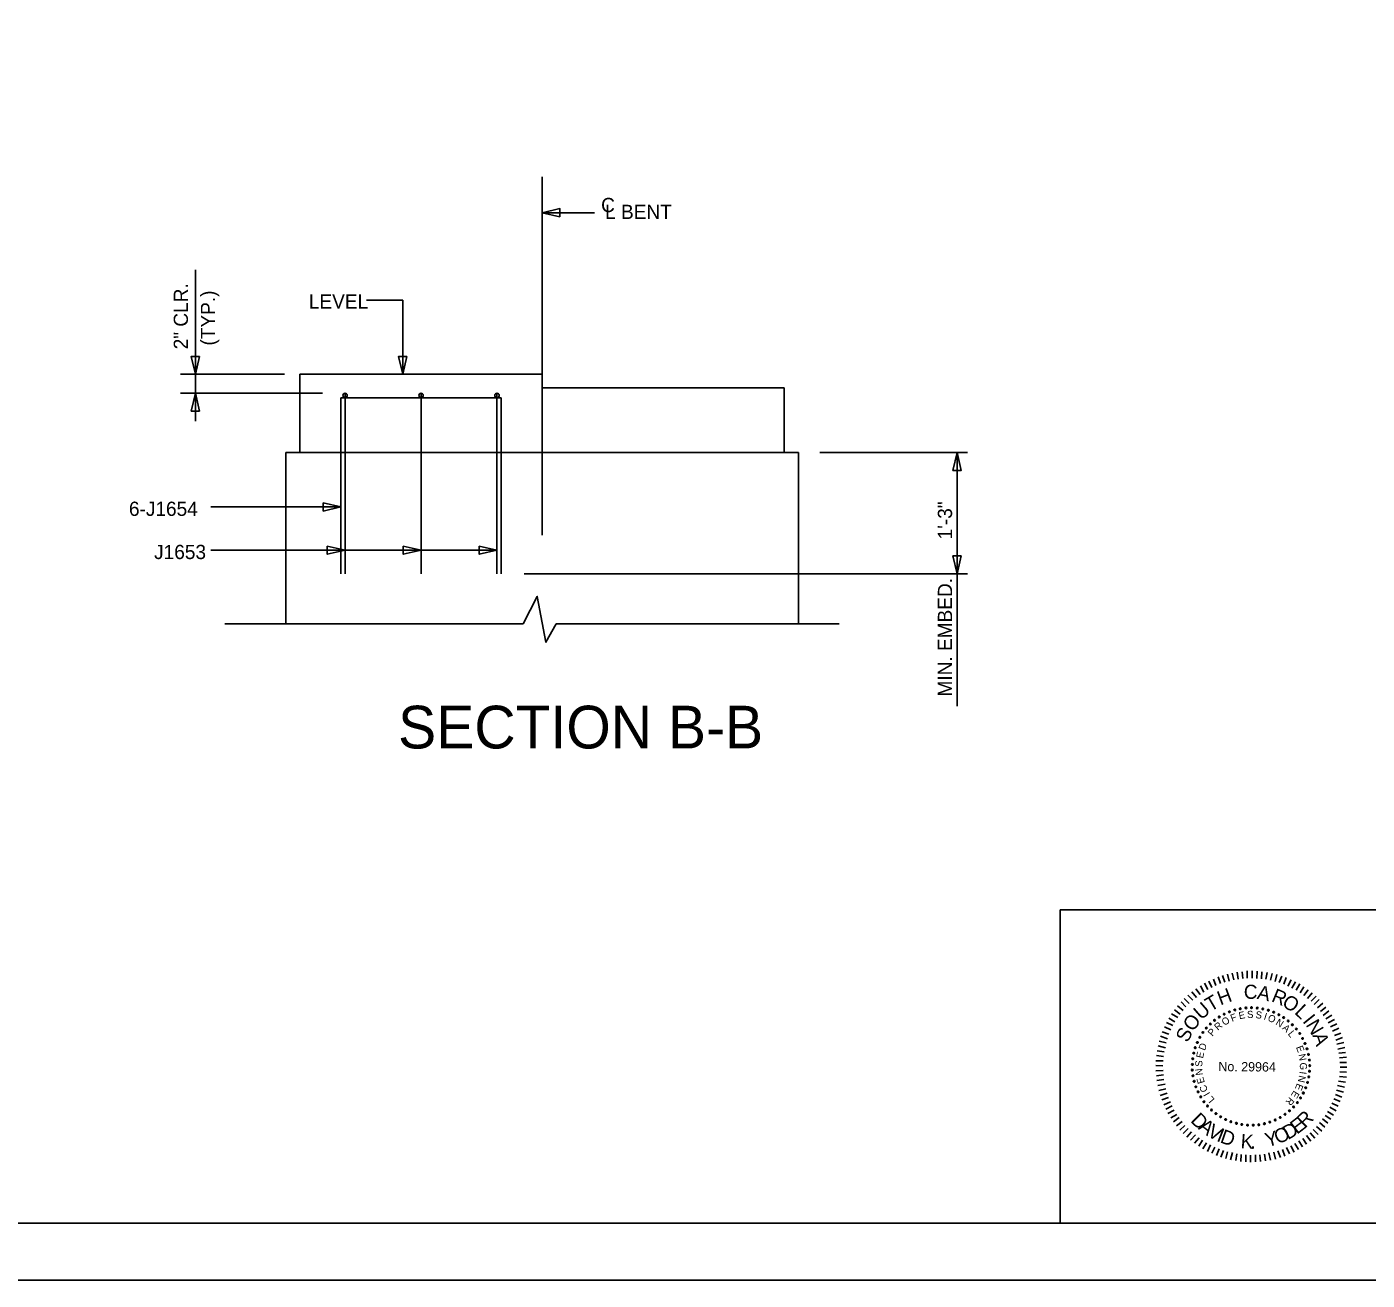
# Model space of a CAD drawing. Extents: x -133.1 to -97, y -58.4 to -36.4.
# Drawn here: x -119.58 to -107.81, y -58.4 to -47.4 of the extents above; entities that cross this region are included whole.
import ezdxf

# ---------------------------------------------------------------- set-up
doc = ezdxf.new("R2010")
doc.units = 0
for name, color, linetype in [('BR_AUTO DIMENSION', 7, 'Continuous'), ('BR_BORDER LINES', 7, 'Continuous'), ('BR_CENTER LINES', 7, 'Continuous'), ('BR_CONCRETE', 7, 'Continuous'), ('BR_REBAR', 7, 'Continuous'), ('BR_TEXT', 7, 'Continuous'), ('Default', 7, 'Continuous'), ('Level 31', 7, 'Continuous')]:
    doc.layers.add(name, color=color, linetype=linetype)

msp = doc.modelspace()

# ---------------------------------------------------------------- linework, layer by layer
at = {"layer": 'BR_AUTO DIMENSION'}
for p, q in [((-115.055, -49.03), (-114.595, -49.03)), ((-118.098, -49.531), (-118.098, -50.859)), ((-116.595, -49.798), (-116.278, -49.798)), ((-116.278, -49.798), (-116.278, -50.448)), ((-117.315, -50.448), (-118.229, -50.448)), ((-116.982, -50.615), (-118.229, -50.615)), ((-112.618, -51.136), (-111.323, -51.136)), ((-111.413, -51.136), (-111.413, -53.362)), ((-116.82, -51.612), (-117.962, -51.612)), ((-115.451, -51.992), (-117.962, -51.992)), ((-116.992, -51.992), (-117.072, -51.992)), ((-116.117, -51.992), (-116.197, -51.992)), ((-115.451, -51.992), (-115.531, -51.992)), ((-115.213, -52.198), (-111.323, -52.198))]:
    msp.add_line(p, q, dxfattribs=at)
for points in [[(-114.899, -49.066), (-115.055, -49.03), (-114.899, -48.994)], [(-118.062, -50.292), (-118.098, -50.448), (-118.134, -50.292)], [(-116.242, -50.292), (-116.278, -50.448), (-116.314, -50.292)], [(-118.134, -50.771), (-118.098, -50.615), (-118.062, -50.771)], [(-111.449, -51.292), (-111.413, -51.136), (-111.377, -51.292)], [(-116.976, -51.576), (-116.82, -51.612), (-116.976, -51.648)], [(-116.94, -51.956), (-116.784, -51.992), (-116.94, -52.028)], [(-116.273, -51.956), (-116.117, -51.992), (-116.273, -52.028)], [(-115.607, -51.956), (-115.451, -51.992), (-115.607, -52.028)], [(-111.377, -52.042), (-111.413, -52.198), (-111.449, -52.042)]]:
    msp.add_lwpolyline(points, close=True, dxfattribs=at)
at = {"layer": 'BR_BORDER LINES'}
for p, q in [((-110.507, -55.149), (-105.142, -55.149)), ((-110.507, -57.899), (-110.507, -55.149)), ((-131.308, -57.899), (-97.642, -57.899))]:
    msp.add_line(p, q, dxfattribs=at)
at = {"layer": 'BR_CENTER LINES'}
msp.add_line((-115.055, -51.86), (-115.055, -48.715), dxfattribs=at)
at = {"layer": 'BR_CONCRETE'}
for p, q in [((-117.18, -50.448), (-117.18, -51.136)), ((-117.18, -50.448), (-115.055, -50.448)), ((-115.055, -50.448), (-115.055, -51.136)), ((-115.055, -50.566), (-112.93, -50.566)), ((-112.93, -50.566), (-112.93, -51.136)), ((-117.305, -52.638), (-117.305, -51.136)), ((-117.305, -51.136), (-112.805, -51.136)), ((-117.305, -51.136), (-112.805, -51.136)), ((-112.805, -52.638), (-112.805, -51.136))]:
    msp.add_line(p, q, dxfattribs=at)
at = {"layer": 'BR_REBAR'}
for p, q in [((-116.82, -50.654), (-116.82, -52.198)), ((-116.82, -50.654), (-115.414, -50.654)), ((-116.784, -50.615), (-116.784, -52.198)), ((-116.117, -50.615), (-116.117, -52.198)), ((-115.451, -50.615), (-115.451, -52.198)), ((-115.414, -50.654), (-115.414, -52.198))]:
    msp.add_line(p, q, dxfattribs=at)
for centre in [(-116.784, -50.634), (-116.117, -50.634), (-115.451, -50.634)]:
    msp.add_circle(centre, 0.0195, dxfattribs=at)
at = {"layer": 'BR_TEXT'}
for p, q in [((-116.278, -50.448), (-116.278, -50.383)), ((-109.141, -55.812), (-109.164, -55.756)), ((-109.102, -55.795), (-109.123, -55.737)), ((-109.062, -55.783), (-109.084, -55.725)), ((-109.026, -55.773), (-109.039, -55.712)), ((-108.985, -55.763), (-108.999, -55.704)), ((-108.945, -55.756), (-108.954, -55.695)), ((-108.906, -55.752), (-108.91, -55.691)), ((-108.866, -55.749), (-108.866, -55.685)), ((-108.824, -55.747), (-108.824, -55.685)), ((-108.782, -55.75), (-108.78, -55.686)), ((-108.742, -55.753), (-108.737, -55.692)), ((-108.703, -55.758), (-108.693, -55.697)), ((-108.663, -55.766), (-108.649, -55.706)), ((-108.622, -55.776), (-108.606, -55.715)), ((-108.585, -55.787), (-108.563, -55.73)), ((-108.546, -55.8), (-108.524, -55.742)), ((-109.312, -55.917), (-109.352, -55.867)), ((-109.279, -55.892), (-109.318, -55.841)), ((-109.248, -55.871), (-109.278, -55.816)), ((-109.212, -55.847), (-109.243, -55.793)), ((-109.178, -55.829), (-109.204, -55.773)), ((-108.51, -55.817), (-108.482, -55.762)), ((-108.474, -55.835), (-108.443, -55.779)), ((-108.436, -55.853), (-108.404, -55.799)), ((-108.403, -55.878), (-108.369, -55.824)), ((-108.37, -55.899), (-108.333, -55.849)), ((-108.337, -55.925), (-108.297, -55.876)), ((-109.429, -56.031), (-109.479, -55.992)), ((-109.404, -56), (-109.447, -55.957)), ((-109.375, -55.969), (-109.419, -55.925)), ((-109.345, -55.942), (-109.387, -55.897)), ((-108.306, -55.95), (-108.263, -55.906)), ((-108.278, -55.978), (-108.235, -55.935)), ((-108.25, -56.009), (-108.202, -55.968)), ((-109.501, -56.13), (-109.555, -56.098)), ((-109.477, -56.094), (-109.531, -56.06)), ((-109.455, -56.065), (-109.505, -56.025)), ((-108.223, -56.041), (-108.176, -56.003)), ((-108.199, -56.075), (-108.15, -56.036)), ((-108.177, -56.104), (-108.124, -56.072)), ((-108.155, -56.141), (-108.101, -56.11)), ((-109.554, -56.24), (-109.612, -56.218)), ((-109.536, -56.201), (-109.593, -56.176)), ((-109.519, -56.164), (-109.575, -56.137)), ((-108.137, -56.176), (-108.079, -56.149)), ((-108.119, -56.213), (-108.062, -56.188)), ((-109.585, -56.358), (-109.648, -56.342)), ((-109.578, -56.316), (-109.639, -56.301)), ((-109.566, -56.28), (-109.627, -56.257)), ((-108.102, -56.252), (-108.046, -56.231)), ((-108.089, -56.292), (-108.031, -56.27)), ((-108.079, -56.328), (-108.019, -56.314)), ((-109.601, -56.435), (-109.662, -56.428)), ((-109.596, -56.394), (-109.657, -56.386)), ((-108.071, -56.37), (-108.011, -56.355)), ((-108.063, -56.406), (-108.003, -56.399)), ((-108.056, -56.448), (-107.995, -56.441)), ((-109.604, -56.558), (-109.669, -56.56)), ((-109.604, -56.474), (-109.668, -56.474)), ((-109.606, -56.516), (-109.668, -56.515)), ((-108.055, -56.487), (-107.995, -56.488)), ((-108.055, -56.571), (-107.995, -56.573)), ((-108.052, -56.528), (-107.991, -56.529)), ((-109.602, -56.597), (-109.664, -56.604)), ((-109.598, -56.638), (-109.659, -56.647)), ((-109.588, -56.678), (-109.651, -56.691)), ((-108.073, -56.69), (-108.013, -56.705)), ((-108.065, -56.651), (-108.005, -56.661)), ((-108.057, -56.61), (-107.996, -56.618)), ((-109.582, -56.72), (-109.643, -56.734)), ((-109.57, -56.757), (-109.632, -56.778)), ((-109.558, -56.796), (-109.617, -56.817)), ((-108.107, -56.808), (-108.051, -56.83)), ((-108.093, -56.769), (-108.036, -56.791)), ((-108.082, -56.732), (-108.022, -56.747)), ((-109.541, -56.833), (-109.599, -56.86)), ((-109.524, -56.869), (-109.581, -56.899)), ((-109.508, -56.906), (-109.562, -56.937)), ((-108.161, -56.917), (-108.108, -56.949)), ((-108.143, -56.88), (-108.086, -56.911)), ((-108.125, -56.844), (-108.068, -56.872)), ((-109.484, -56.943), (-109.538, -56.974)), ((-109.463, -56.972), (-109.513, -57.009)), ((-109.437, -57.006), (-109.487, -57.045)), ((-109.413, -57.04), (-109.457, -57.081)), ((-108.258, -57.049), (-108.212, -57.091)), ((-108.231, -57.016), (-108.185, -57.056)), ((-108.206, -56.983), (-108.158, -57.02)), ((-108.184, -56.954), (-108.132, -56.986)), ((-109.384, -57.066), (-109.429, -57.111)), ((-109.355, -57.096), (-109.397, -57.142)), ((-109.322, -57.122), (-109.363, -57.169)), ((-109.289, -57.148), (-109.329, -57.196)), ((-109.258, -57.17), (-109.29, -57.222)), ((-108.38, -57.156), (-108.345, -57.204)), ((-108.347, -57.13), (-108.308, -57.178)), ((-108.315, -57.105), (-108.273, -57.151)), ((-108.287, -57.075), (-108.244, -57.121)), ((-109.223, -57.192), (-109.255, -57.246)), ((-109.189, -57.212), (-109.216, -57.268)), ((-109.152, -57.23), (-109.177, -57.285)), ((-109.114, -57.247), (-109.136, -57.304)), ((-109.075, -57.26), (-109.097, -57.318)), ((-109.039, -57.272), (-109.053, -57.331)), ((-108.997, -57.279), (-109.013, -57.341)), ((-108.676, -57.282), (-108.662, -57.344)), ((-108.634, -57.275), (-108.619, -57.335)), ((-108.597, -57.264), (-108.576, -57.322)), ((-108.558, -57.252), (-108.537, -57.309)), ((-108.522, -57.235), (-108.495, -57.291)), ((-108.485, -57.218), (-108.455, -57.274)), ((-108.448, -57.199), (-108.416, -57.253)), ((-108.414, -57.177), (-108.381, -57.229)), ((-108.958, -57.291), (-108.968, -57.349)), ((-108.919, -57.295), (-108.923, -57.357)), ((-108.879, -57.298), (-108.88, -57.36)), ((-108.837, -57.301), (-108.838, -57.362)), ((-108.795, -57.299), (-108.794, -57.361)), ((-108.755, -57.297), (-108.751, -57.358)), ((-108.716, -57.293), (-108.706, -57.351))]:
    msp.add_line(p, q, dxfattribs=at)
for centre, start, end in [((-109.153, -56.117), 38.2961, 218.2961), ((-109.112, -56.088), 32.7576, 212.7576), ((-109.112, -56.088), 212.7576, 32.7576), ((-109.069, -56.064), 27.2191, 207.2191), ((-109.069, -56.064), 207.2191, 27.2191), ((-109.023, -56.043), 21.6807, 201.6807), ((-109.023, -56.043), 201.6807, 21.6807), ((-108.976, -56.027), 16.1422, 196.1422), ((-108.976, -56.027), 196.1422, 16.1422), ((-108.928, -56.016), 10.6038, 190.6038), ((-108.928, -56.016), 190.6038, 10.6038), ((-108.878, -56.009), 5.0653, 185.0653), ((-108.878, -56.009), 185.0653, 5.0653), ((-108.829, -56.007), 359.5268, 179.5268), ((-108.829, -56.007), 179.5268, 359.5268), ((-108.779, -56.01), 353.9884, 173.9884), ((-108.779, -56.01), 173.9884, 353.9884), ((-108.73, -56.018), 168.4499, 348.4499), ((-108.73, -56.018), 348.4499, 168.4499), ((-108.681, -56.03), 342.9114, 162.9114), ((-108.681, -56.03), 162.9114, 342.9114), ((-108.635, -56.047), 157.373, 337.373), ((-108.635, -56.047), 337.373, 157.373), ((-108.59, -56.069), 151.8345, 331.8345), ((-108.59, -56.069), 331.8345, 151.8345), ((-108.547, -56.094), 146.2961, 326.2961), ((-108.547, -56.094), 326.2961, 146.2961), ((-109.255, -56.225), 54.9114, 234.9114), ((-109.255, -56.225), 234.9114, 54.9114), ((-109.225, -56.186), 49.373, 229.373), ((-109.225, -56.186), 229.373, 49.373), ((-109.19, -56.15), 43.8345, 223.8345), ((-109.19, -56.15), 223.8345, 43.8345), ((-109.153, -56.117), 218.2961, 38.2961), ((-108.507, -56.124), 140.7576, 320.7576), ((-108.507, -56.124), 320.7576, 140.7576), ((-108.47, -56.157), 135.2191, 315.2191), ((-108.47, -56.157), 315.2191, 135.2191), ((-108.436, -56.194), 129.6807, 309.6807), ((-108.436, -56.194), 309.6807, 129.6807), ((-108.406, -56.234), 124.1422, 304.1422), ((-108.406, -56.234), 304.1422, 124.1422), ((-109.305, -56.312), 65.9884, 245.9884), ((-109.305, -56.312), 245.9884, 65.9884), ((-109.282, -56.267), 60.4499, 240.4499), ((-109.282, -56.267), 240.4499, 60.4499), ((-108.381, -56.277), 118.6038, 298.6038), ((-108.381, -56.277), 298.6038, 118.6038), ((-108.359, -56.322), 113.0653, 293.0653), ((-108.359, -56.322), 293.0653, 113.0653), ((-109.345, -56.455), 82.6038, 262.6038), ((-109.345, -56.455), 262.6038, 82.6038), ((-109.336, -56.406), 77.0653, 257.0653), ((-109.336, -56.406), 257.0653, 77.0653), ((-109.323, -56.358), 71.5268, 251.5268), ((-109.323, -56.358), 251.5268, 71.5268), ((-108.342, -56.368), 107.5268, 287.5268), ((-108.342, -56.368), 287.5268, 107.5268), ((-108.329, -56.417), 101.9884, 281.9884), ((-108.329, -56.417), 281.9884, 101.9884), ((-108.321, -56.466), 96.4499, 276.4499), ((-108.321, -56.466), 276.4499, 96.4499), ((-109.349, -56.505), 88.1422, 268.1422), ((-109.349, -56.555), 93.6807, 273.6807), ((-109.349, -56.505), 268.1422, 88.1422), ((-109.349, -56.555), 273.6807, 93.6807), ((-108.32, -56.565), 85.373, 265.373), ((-108.318, -56.516), 90.9114, 270.9114), ((-108.32, -56.565), 265.373, 85.373), ((-108.318, -56.516), 270.9114, 90.9114), ((-109.343, -56.604), 99.2191, 279.2191), ((-109.343, -56.604), 279.2191, 99.2191), ((-109.333, -56.653), 104.7576, 284.7576), ((-109.333, -56.653), 284.7576, 104.7576), ((-109.318, -56.701), 110.2961, 290.2961), ((-109.318, -56.701), 290.2961, 110.2961), ((-108.338, -56.663), 74.2961, 254.2961), ((-108.338, -56.663), 254.2961, 74.2961), ((-108.326, -56.615), 79.8345, 259.8345), ((-108.326, -56.615), 259.8345, 79.8345), ((-109.298, -56.746), 115.8345, 295.8345), ((-109.298, -56.746), 295.8345, 115.8345), ((-109.275, -56.79), 121.373, 301.373), ((-109.275, -56.79), 301.373, 121.373), ((-108.399, -56.799), 57.6807, 237.6807), ((-108.399, -56.799), 237.6807, 57.6807), ((-108.374, -56.756), 63.2191, 243.2191), ((-108.374, -56.756), 243.2191, 63.2191), ((-108.354, -56.71), 68.7576, 248.7576), ((-108.354, -56.71), 248.7576, 68.7576), ((-109.247, -56.832), 126.9114, 306.9114), ((-109.247, -56.832), 306.9114, 126.9114), ((-109.215, -56.87), 132.4499, 312.4499), ((-109.215, -56.87), 312.4499, 132.4499), ((-109.18, -56.905), 137.9884, 317.9884), ((-109.18, -56.905), 317.9884, 137.9884), ((-109.141, -56.937), 143.5268, 323.5268), ((-109.141, -56.937), 323.5268, 143.5268), ((-108.496, -56.912), 41.0653, 221.0653), ((-108.496, -56.912), 221.0653, 41.0653), ((-108.46, -56.878), 46.6038, 226.6038), ((-108.46, -56.878), 226.6038, 46.6038), ((-108.427, -56.84), 52.1422, 232.1422), ((-108.427, -56.84), 232.1422, 52.1422), ((-109.1, -56.965), 149.0653, 329.0653), ((-109.1, -56.965), 329.0653, 149.0653), ((-109.056, -56.988), 154.6038, 334.6038), ((-109.056, -56.988), 334.6038, 154.6038), ((-109.01, -57.007), 340.1422, 160.1422), ((-109.01, -57.007), 160.1422, 340.1422), ((-108.962, -57.022), 345.6807, 165.6807), ((-108.962, -57.022), 165.6807, 345.6807), ((-108.914, -57.032), 351.2191, 171.2191), ((-108.914, -57.032), 171.2191, 351.2191), ((-108.864, -57.038), 356.7576, 176.7576), ((-108.864, -57.038), 176.7576, 356.7576), ((-108.814, -57.038), 2.2961, 182.2961), ((-108.814, -57.038), 182.2961, 2.2961), ((-108.765, -57.034), 7.8345, 187.8345), ((-108.765, -57.034), 187.8345, 7.8345), ((-108.716, -57.025), 13.373, 193.373), ((-108.716, -57.025), 193.373, 13.373), ((-108.668, -57.011), 18.9114, 198.9114), ((-108.668, -57.011), 198.9114, 18.9114), ((-108.621, -56.993), 24.4499, 204.4499), ((-108.621, -56.993), 204.4499, 24.4499), ((-108.577, -56.97), 29.9884, 209.9884), ((-108.577, -56.97), 209.9884, 29.9884), ((-108.535, -56.943), 35.5268, 215.5268), ((-108.535, -56.943), 215.5268, 35.5268)]:
    msp.add_arc(centre, 0.00701, start, end, dxfattribs=at)
at = {"layer": 'Default'}
for p, q in [((-117.838, -52.638), (-115.221, -52.638)), ((-114.933, -52.638), (-112.449, -52.638))]:
    msp.add_line(p, q, dxfattribs=at)
msp.add_lwpolyline([(-114.933, -52.638), (-115.022, -52.8), (-115.097, -52.398), (-115.221, -52.638)], dxfattribs=at)
at = {"layer": 'Level 31'}
msp.add_lwpolyline([(-133.141, -58.399), (-97.141, -58.399), (-97.141, -36.399), (-133.141, -36.399)], close=True, dxfattribs=at)

# ---------------------------------------------------------------- texts
at = {"layer": 'BR_AUTO DIMENSION'}
for s, p in [('C', (-114.537, -49.025)), ('L BENT', (-114.502, -49.085)), ('LEVEL', (-117.102, -49.871)), ('6-J1654', (-118.681, -51.691)), ('J1653', (-118.46, -52.07))]:
    msp.add_text(s, height=0.125, dxfattribs=at).set_placement(p)
for s, p in [('2" CLR.', (-118.163, -50.229)), ('(TYP.)', (-117.925, -50.196)), ('1\'-3" ', (-111.457, -51.897)), ('MIN. EMBED.', (-111.457, -53.276))]:
    msp.add_text(s, height=0.125, rotation=90, dxfattribs=at).set_placement(p)
at = {"layer": 'BR_TEXT'}
msp.add_text('SECTION B-B', height=0.375, dxfattribs=at).set_placement((-116.319, -53.732))
for s, height, rotation, p in [('H', 0.124, 20.3637, (-109.102, -55.988)), ('C', 0.124, 359.5482, (-108.897, -55.929)), ('A', 0.124, 348.1981, (-108.786, -55.929)), ('R', 0.124, 337.4344, (-108.662, -55.949)), ('U', 0.124, 40.8022, (-109.271, -56.12)), ('T', 0.124, 30.4992, (-109.189, -56.045)), ('O', 0.124, 326.5869, (-108.57, -55.985)), ('L', 0.124, 315.9488, (-108.458, -56.053)), ('O', 0.124, 52.0267, (-109.345, -56.224)), ('O', 0.0622, 30.8477, (-109.068, -56.167)), ('F', 0.0622, 20.6127, (-109, -56.131)), ('E', 0.0622, 11.4103, (-108.935, -56.109)), ('S', 0.0622, 2.208, (-108.867, -56.098)), ('S', 0.0622, 352.6608, (-108.796, -56.098)), ('I', 0.0622, 343.1136, (-108.726, -56.11)), ('O', 0.0622, 338.4392, (-108.692, -56.12)), ('N', 0.0622, 328.2042, (-108.623, -56.152)), ('I', 0.124, 308.6613, (-108.386, -56.127)), ('N', 0.124, 300.7037, (-108.356, -56.157)), ('S', 0.124, 63.2511, (-109.39, -56.32)), ('P', 0.0622, 49.9421, (-109.172, -56.263)), ('R', 0.0622, 40.3949, (-109.124, -56.211)), ('A', 0.0622, 318.657, (-108.564, -56.192)), ('L', 0.0622, 309.4546, (-108.514, -56.239)), ('D', 0.0622, 69.0364, (-109.239, -56.388)), ('E', 0.0622, 291.049, (-108.44, -56.354)), ('A', 0.124, 289.4792, (-108.296, -56.25)), ('E', 0.0622, 78.2388, (-109.255, -56.455)), ('N', 0.0622, 281.8466, (-108.418, -56.419)), ('S', 0.0622, 87.786, (-109.261, -56.526)), ('N', 0.0622, 97.3332, (-109.255, -56.597)), ('No. 29964', 0.0817, 359.5268, (-109.12, -56.564)), ('I', 0.0622, 262.4084, (-108.406, -56.564)), ('G', 0.0622, 272.2995, (-108.406, -56.49)), ('E', 0.0622, 106.5355, (-109.238, -56.664)), ('C', 0.0622, 116.4266, (-109.208, -56.731)), ('E', 0.0622, 248.1867, (-108.429, -56.667)), ('N', 0.0622, 257.7339, (-108.411, -56.598)), ('I', 0.0622, 121.1011, (-109.19, -56.761)), ('L', 0.0622, 129.9595, (-109.149, -56.813)), ('R', 0.0622, 229.782, (-108.495, -56.787)), ('E', 0.0622, 238.9844, (-108.457, -56.73)), ('D', 0.124, 315.4053, (-109.37, -57.004)), ('R', 0.124, 44.5947, (-108.359, -57.069)), ('A', 0.124, 322.8377, (-109.303, -57.069)), ('V', 0.124, 330.5179, (-109.226, -57.128)), ('D', 0.124, 30.1015, (-108.51, -57.17)), ('E', 0.124, 37.5339, (-108.43, -57.123)), ('I', 0.124, 338.1981, (-109.142, -57.175)), ('D', 0.124, 340.7995, (-109.112, -57.188)), ('K', 0.124, 356.098, (-108.927, -57.239)), ('Y', 0.124, 14.8649, (-108.692, -57.232)), ('O', 0.124, 22.4212, (-108.6, -57.207)), ('.', 0.124, 3.1588, (-108.838, -57.245))]:
    msp.add_text(s, height=height, rotation=rotation, dxfattribs=at).set_placement(p)

doc.saveas('drawing.dxf')
